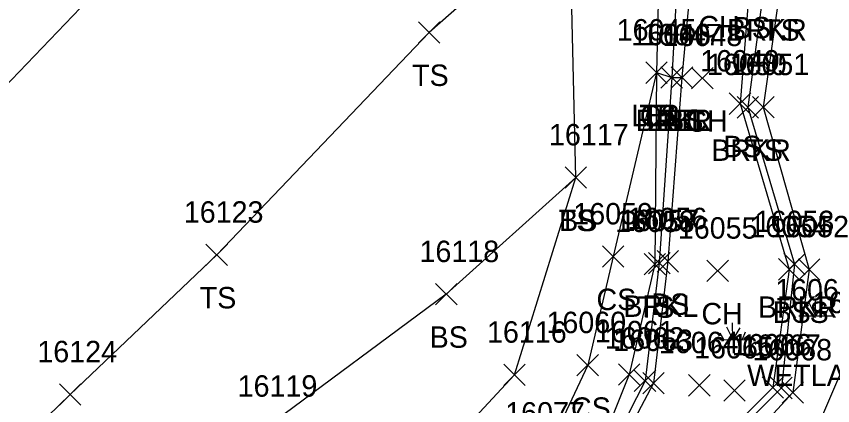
# Model space of a CAD drawing. Extents: x 1606530 to 1613020, y 784959 to 789666.
# Drawn here: x 1609253.6 to 1609329.8, y 788511.7 to 788548 of the extents above; entities that cross this region are included whole.
import ezdxf

# ---------------------------------------------------------------- set-up
doc = ezdxf.new("R2010")
doc.units = 0
for name, color, linetype in [('L_A', 7, 'Continuous'), ('L_I', 7, 'Continuous'), ('L_TIC', 7, 'Continuous'), ('LARO', 7, 'Continuous'), ('LAWE', 7, 'Continuous'), ('LELB', 7, 'Continuous'), ('LWET', 7, 'Continuous')]:
    doc.layers.add(name, color=color, linetype=linetype)

msp = doc.modelspace()

# ---------------------------------------------------------------- linework, layer by layer
at = {"layer": 'L_TIC'}
for points in [[(1609291.123, 788545.533), (1609293.123, 788547.533)], [(1609293.123, 788545.533), (1609291.123, 788547.533)], [(1609312.343, 788541.776), (1609314.343, 788543.776)], [(1609314.343, 788541.776), (1609312.343, 788543.776)], [(1609312.343, 788541.776), (1609314.343, 788543.776)], [(1609314.343, 788541.776), (1609312.343, 788543.776)], [(1609312.343, 788541.776), (1609314.343, 788543.776)], [(1609314.343, 788541.776), (1609312.343, 788543.776)], [(1609313.764, 788541.332), (1609315.764, 788543.332)], [(1609315.764, 788541.332), (1609313.764, 788543.332)], [(1609313.764, 788541.332), (1609315.764, 788543.332)], [(1609315.764, 788541.332), (1609313.764, 788543.332)], [(1609314.721, 788541.334), (1609316.721, 788543.334)], [(1609316.721, 788541.334), (1609314.721, 788543.334)], [(1609314.721, 788541.334), (1609316.721, 788543.334)], [(1609316.721, 788541.334), (1609314.721, 788543.334)], [(1609314.721, 788541.334), (1609316.721, 788543.334)], [(1609316.721, 788541.334), (1609314.721, 788543.334)], [(1609316.626, 788541.26), (1609318.626, 788543.26)], [(1609318.626, 788541.26), (1609316.626, 788543.26)], [(1609320.14, 788538.885), (1609322.14, 788540.885)], [(1609322.14, 788538.885), (1609320.14, 788540.885)], [(1609320.859, 788538.543), (1609322.859, 788540.543)], [(1609322.859, 788538.543), (1609320.859, 788540.543)], [(1609322.314, 788538.546), (1609324.314, 788540.546)], [(1609324.314, 788538.546), (1609322.314, 788540.546)], [(1609304.812, 788531.988), (1609306.812, 788533.988)], [(1609306.812, 788531.988), (1609304.812, 788533.988)], [(1609304.812, 788531.988), (1609306.812, 788533.988)], [(1609306.812, 788531.988), (1609304.812, 788533.988)], [(1609271.297, 788524.77), (1609273.297, 788526.77)], [(1609273.297, 788524.77), (1609271.297, 788526.77)], [(1609308.302, 788524.609), (1609310.302, 788526.609)], [(1609310.302, 788524.609), (1609308.302, 788526.609)], [(1609312.191, 788523.895), (1609314.191, 788525.895)], [(1609314.191, 788523.895), (1609312.191, 788525.895)], [(1609312.606, 788523.981), (1609314.606, 788525.981)], [(1609314.606, 788523.981), (1609312.606, 788525.981)], [(1609313.405, 788524.163), (1609315.405, 788526.163)], [(1609315.405, 788524.163), (1609313.405, 788526.163)], [(1609325.22, 788523.89), (1609327.22, 788525.89)], [(1609327.22, 788523.89), (1609325.22, 788525.89)], [(1609318.051, 788523.281), (1609320.051, 788525.281)], [(1609320.051, 788523.281), (1609318.051, 788525.281)], [(1609324.729, 788523.414), (1609326.729, 788525.414)], [(1609326.729, 788523.414), (1609324.729, 788525.414)], [(1609326.591, 788523.41), (1609328.591, 788525.41)], [(1609328.591, 788523.41), (1609326.591, 788525.41)], [(1609292.728, 788521.094), (1609294.728, 788523.094)], [(1609294.728, 788521.094), (1609292.728, 788523.094)], [(1609305.922, 788514.462), (1609307.922, 788516.462)], [(1609307.922, 788514.462), (1609305.922, 788516.462)], [(1609299.084, 788513.569), (1609301.084, 788515.569)], [(1609301.084, 788513.569), (1609299.084, 788515.569)], [(1609309.792, 788513.607), (1609311.792, 788515.607)], [(1609311.792, 788513.607), (1609309.792, 788515.607)], [(1609311.272, 788513.017), (1609313.272, 788515.017)], [(1609313.272, 788513.017), (1609311.272, 788515.017)], [(1609312.075, 788512.791), (1609314.075, 788514.791)], [(1609314.075, 788512.791), (1609312.075, 788514.791)], [(1609316.338, 788512.59), (1609318.338, 788514.59)], [(1609318.338, 788512.59), (1609316.338, 788514.59)], [(1609257.625, 788511.741), (1609259.625, 788513.741)], [(1609259.625, 788511.741), (1609257.625, 788513.741)], [(1609319.618, 788512.098), (1609321.618, 788514.098)], [(1609321.618, 788512.098), (1609319.618, 788514.098)], [(1609323.195, 788512.38), (1609325.195, 788514.38)], [(1609325.195, 788512.38), (1609323.195, 788514.38)], [(1609323.997, 788512.339), (1609325.997, 788514.339)], [(1609325.997, 788512.339), (1609323.997, 788514.339)], [(1609325.059, 788511.915), (1609327.059, 788513.915)], [(1609327.059, 788511.915), (1609325.059, 788513.915)]]:
    msp.add_lwpolyline(points, dxfattribs=at)
at = {"layer": 'LARO'}
for points in [[(1609318.065, 788560.519), (1609316.696, 788553.061), (1609315.721, 788542.334)], [(1609313.597, 788553.251), (1609313.343, 788542.776), (1609314.764, 788542.332), (1609315.721, 788542.334)]]:
    msp.add_lwpolyline(points, dxfattribs=at)
at = {"layer": 'LAWE'}
for points in [[(1609338.265, 788592.862), (1609325.525, 788576.58), (1609316.807, 788561.044), (1609315.365, 788553.22), (1609314.764, 788542.332), (1609313.606, 788524.981), (1609312.272, 788514.017), (1609308.3, 788506.198), (1609303.822, 788499.065), (1609298.927, 788492.769), (1609297.256, 788491.801), (1609294.184, 788489.575), (1609292.29, 788488.306), (1609291.476, 788483.291), (1609293.319, 788483.357)], [(1609344.132, 788584.453), (1609332.99, 788571.865), (1609323.348, 788550.774), (1609321.859, 788539.543), (1609326.22, 788524.89), (1609324.997, 788513.339), (1609315.185, 788503.575), (1609311.383, 788494.432), (1609306.343, 788485.871), (1609298.451, 788485.655), (1609293.319, 788483.357)]]:
    msp.add_lwpolyline(points, dxfattribs=at)
at = {"layer": 'LELB'}
for points in [[(1609319.772, 788603.268), (1609301.366, 788576.738), (1609263.879, 788553.328), (1609243.1, 788531.637), (1609229.418, 788508.615), (1609199.998, 788494.814), (1609187.997, 788508.21), (1609183.647, 788514.965), (1609192.671, 788532.692), (1609206.541, 788560.831)], [(1609345.504, 788583.398), (1609333.653, 788571.33), (1609324.885, 788550.763), (1609323.314, 788539.546), (1609327.591, 788524.41), (1609326.059, 788512.915), (1609316.424, 788502.417), (1609312.433, 788493.737), (1609309.548, 788485.41), (1609300.66, 788483.185), (1609295.698, 788481.162), (1609290.687, 788481.419), (1609288.118, 788482.434), (1609286.783, 788487.092), (1609286.122, 788490.996), (1609287.418, 788500.952), (1609300.084, 788514.569), (1609305.812, 788532.988), (1609305.239, 788558.079), (1609320.597, 788588.369), (1609325.511, 788599.313)], [(1609344.018, 788584.804), (1609331.2, 788572.095), (1609322.01, 788550.979), (1609321.14, 788539.885), (1609325.729, 788524.414), (1609324.195, 788513.38), (1609314.539, 788503.632), (1609310.988, 788495.081), (1609306.001, 788487.028), (1609297.097, 788486.905)], [(1609366.827, 788579.614), (1609348.341, 788574.614), (1609345.128, 788559.502), (1609339.409, 788545.413), (1609353.526, 788532.076), (1609355.901, 788515.928), (1609350.146, 788501.166), (1609342.753, 788489.296), (1609336.962, 788484.436), (1609343.274, 788499.194), (1609340.298, 788515.898), (1609331.632, 788517.324), (1609323.809, 788499.051), (1609313.667, 788488.005), (1609309.548, 788485.41)], [(1609305.239, 788558.079), (1609292.123, 788546.533), (1609272.297, 788525.77), (1609258.625, 788512.741), (1609243.895, 788498.471), (1609227.282, 788490.211), (1609208.034, 788485.11), (1609185.28, 788481.504)], [(1609313.343, 788542.776), (1609313.191, 788524.895), (1609310.792, 788514.607), (1609307.366, 788506.057), (1609303.599, 788500.047), (1609298.055, 788494.668), (1609294.558, 788493.383), (1609291.426, 788493.764), (1609286.122, 788490.996)], [(1609313.343, 788542.776), (1609309.302, 788525.609), (1609306.922, 788515.462), (1609302.939, 788507.019), (1609299.697, 788501.458), (1609296.421, 788495.325), (1609294.558, 788493.383), (1609290.574, 788489.139), (1609286.783, 788487.092)], [(1609315.721, 788542.334), (1609314.405, 788525.163), (1609313.075, 788513.791), (1609308.988, 788506.06), (1609304.305, 788498.934), (1609299.732, 788492.837), (1609295.833, 788488.887), (1609297.097, 788486.905)], [(1609305.812, 788532.988), (1609293.728, 788522.094), (1609276.762, 788509.528), (1609263.732, 788491.487), (1609240.783, 788478.4)]]:
    msp.add_lwpolyline(points, dxfattribs=at)
at = {"layer": 'LWET'}
for p, q in [((1609328.187, 788520.072), (1609328.178, 788521.652)), ((1609326.984, 788520.706), (1609327.37, 788520.063)), ((1609327.59, 788521.258), (1609328.197, 788520.082)), ((1609328.858, 788521.166), (1609328.197, 788520.082)), ((1609329.355, 788520.762), (1609329.061, 788520.082)), ((1609326.635, 788520.063), (1609329.759, 788520.082)), ((1609319.863, 788519.036), (1609320.469, 788517.86)), ((1609320.46, 788517.851), (1609320.451, 788519.431)), ((1609319.257, 788518.485), (1609319.643, 788517.842)), ((1609321.131, 788518.944), (1609320.469, 788517.86)), ((1609321.627, 788518.54), (1609321.333, 788517.86)), ((1609328.187, 788518.51), (1609328.187, 788518.51)), ((1609318.908, 788517.842), (1609322.031, 788517.86)), ((1609320.51, 788517.912), (1609320.469, 788517.912))]:
    msp.add_line(p, q, dxfattribs=at)

# ---------------------------------------------------------------- texts
at = {"layer": 'L_A'}
for s, p in [('CH', (1609317.247, 788546.07)), ('BS', (1609320.451, 788545.979)), ('BRKR', (1609319.938, 788545.774)), ('TS', (1609323.294, 788545.763)), ('TS', (1609290.532, 788541.533)), ('LEL', (1609310.981, 788537.776)), ('TS', (1609311.752, 788537.776)), ('CS', (1609311.784, 788537.776)), ('BRKL', (1609311.41, 788537.332)), ('LEL', (1609312.402, 788537.332)), ('LER', (1609313.304, 788537.334)), ('LEL', (1609313.359, 788537.334)), ('BS', (1609314.162, 788537.334)), ('CH', (1609316.115, 788537.26)), ('BS', (1609319.581, 788534.885)), ('TS', (1609321.724, 788534.546)), ('BRKR', (1609318.449, 788534.543)), ('TS', (1609304.222, 788527.988)), ('BS', (1609304.253, 788527.988)), ('TS', (1609270.707, 788520.77)), ('CS', (1609307.743, 788520.609)), ('BS', (1609312.846, 788520.163)), ('BRKL', (1609310.251, 788519.981)), ('TS', (1609311.601, 788519.895)), ('CH', (1609317.539, 788519.281)), ('BRKR', (1609322.811, 788519.89)), ('BS', (1609324.17, 788519.414)), ('TS', (1609326, 788519.41)), ('BS', (1609292.169, 788517.094)), ('WETLAND', (1609321.802, 788513.51)), ('CS', (1609305.363, 788510.462))]:
    msp.add_text(s, height=2, dxfattribs=at).set_placement(p)
at = {"layer": 'L_I'}
for s, p in [('16045', (1609309.627, 788545.776)), ('16045', (1609309.627, 788545.776)), ('16045', (1609309.627, 788545.776)), ('16046', (1609310.992, 788545.332)), ('16046', (1609310.992, 788545.332)), ('16047', (1609312.005, 788545.334)), ('16047', (1609312.005, 788545.334)), ('16047', (1609312.005, 788545.334)), ('16048', (1609313.91, 788545.26)), ('16049', (1609317.416, 788542.885)), ('16050', (1609318.056, 788542.543)), ('16051', (1609320.165, 788542.546)), ('16117', (1609303.309, 788535.988)), ('16117', (1609303.309, 788535.988)), ('16123', (1609269.226, 788528.77)), ('16059', (1609305.578, 788528.609)), ('16058', (1609309.475, 788527.895)), ('16057', (1609309.889, 788527.981)), ('16056', (1609310.633, 788528.163)), ('16053', (1609322.504, 788527.89)), ('16055', (1609315.335, 788527.281)), ('16054', (1609322.013, 788527.414)), ('16052', (1609323.875, 788527.41)), ('16118', (1609291.224, 788525.094)), ('16069', (1609324.416, 788521.51)), ('16032', (1609327.916, 788520.324)), ('16060', (1609303.072, 788518.462)), ('16116', (1609297.525, 788517.569)), ('16061', (1609307.595, 788517.607)), ('16062', (1609308.509, 788517.017)), ('16063', (1609309.311, 788516.791)), ('16064', (1609313.574, 788516.59)), ('16066', (1609320.376, 788516.38)), ('16067', (1609321.234, 788516.339)), ('16124', (1609255.555, 788515.741)), ('16065', (1609316.854, 788516.098)), ('16068', (1609322.295, 788515.915)), ('16119', (1609274.251, 788512.528)), ('16077', (1609299.223, 788510.019))]:
    msp.add_text(s, height=2, dxfattribs=at).set_placement(p)

doc.saveas('drawing.dxf')
